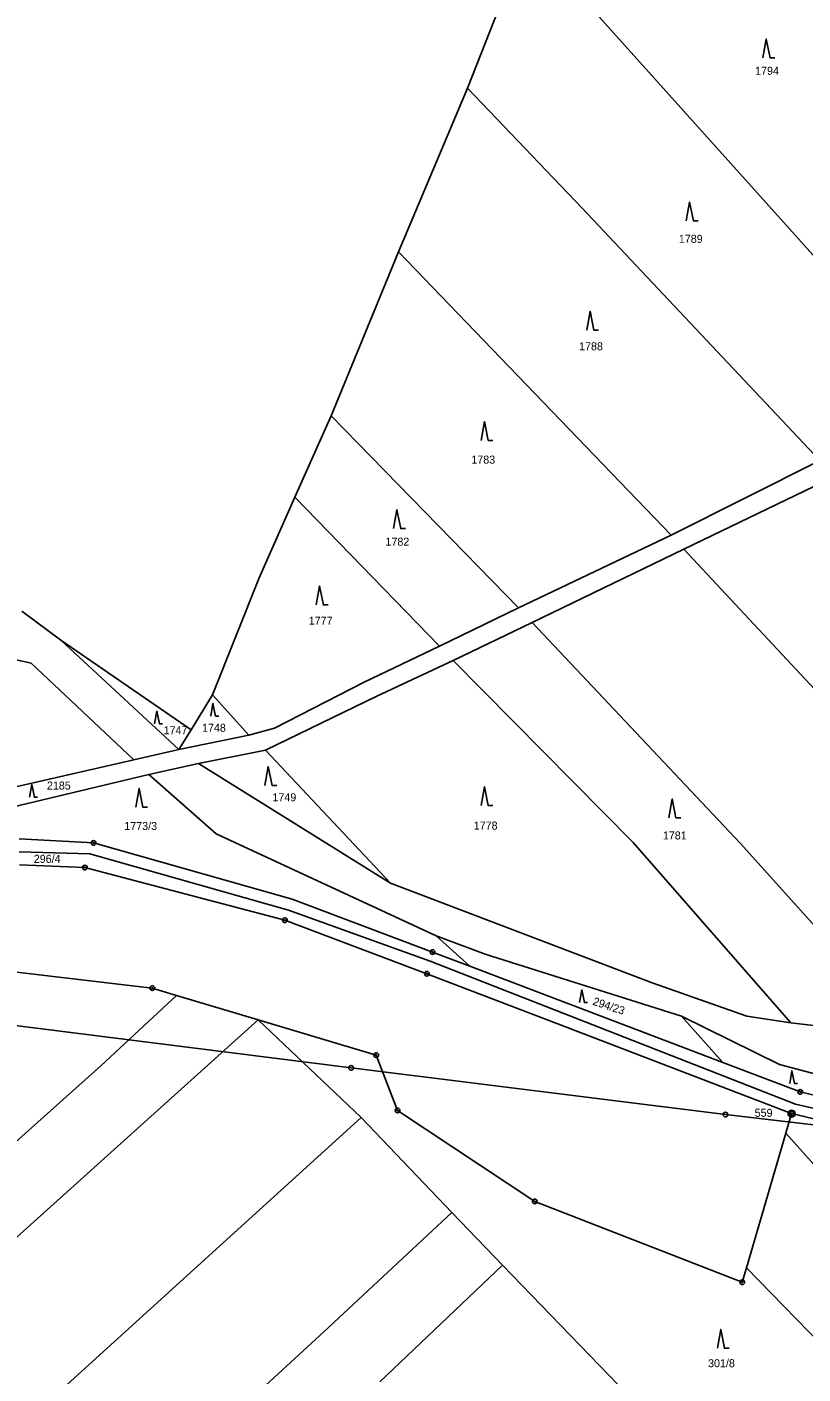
# Model space of a CAD drawing. Extents: x -762263 to -760336, y -1154405 to -1152076.
# Drawn here: x -761289.6 to -761124.8, y -1153787.3 to -1153501.2 of the extents above; entities that cross this region are included whole.
import ezdxf

# ---------------------------------------------------------------- set-up
doc = ezdxf.new("R2010")
doc.units = 0
for name, color, linetype in [('Vrstva 1', 7, 'Continuous'), ('Vrstva 10', 7, 'Continuous'), ('Vrstva 12', 7, 'Continuous'), ('Vrstva 17', 7, 'Continuous'), ('Vrstva 18', 7, 'Continuous'), ('Vrstva 24', 7, 'Continuous'), ('Vrstva 25', 7, 'Continuous'), ('Vrstva 26', 7, 'Continuous'), ('Vrstva 6', 7, 'Continuous')]:
    doc.layers.add(name, color=color, linetype=linetype)

msp = doc.modelspace()

# ---------------------------------------------------------------- linework, layer by layer
at = {"layer": 'Vrstva 1'}
for p, q in [((-761291.26, -1153673.61), (-761275.44, -1153674.5)), ((-761275.44, -1153674.5), (-761233.3, -1153686.44)), ((-761291.2, -1153679.17), (-761277.28, -1153679.74)), ((-761234.81, -1153690.92), (-761277.28, -1153679.74)), ((-761203.44, -1153697.69), (-761233.3, -1153686.44)), ((-761204.67, -1153702.27), (-761234.81, -1153690.92)), ((-761203.44, -1153697.69), (-761195.52, -1153700.7)), ((-761195.52, -1153700.7), (-761141.85, -1153721.11)), ((-761297.23, -1153701.32), (-761262.96, -1153705.34)), ((-761179.48, -1153711.94), (-761204.67, -1153702.27)), ((-761262.96, -1153705.34), (-761257.83, -1153706.88)), ((-761257.83, -1153706.88), (-761240.46, -1153712.08)), ((-761240.46, -1153712.08), (-761215.43, -1153719.57)), ((-761127.23, -1153731.99), (-761179.48, -1153711.94)), ((-761215.43, -1153719.57), (-761210.9, -1153731.31)), ((-761125.37, -1153727.38), (-761141.85, -1153721.11)), ((-761103.58, -1153732.57), (-761125.37, -1153727.38)), ((-761210.9, -1153731.31), (-761181.76, -1153750.64)), ((-761128.45, -1153736.16), (-761127.23, -1153731.99)), ((-761098.09, -1153738.93), (-761127.23, -1153731.99)), ((-761128.45, -1153736.16), (-761136.8, -1153764.7)), ((-761181.76, -1153750.64), (-761137.71, -1153767.8)), ((-761136.8, -1153764.7), (-761137.71, -1153767.8))]:
    msp.add_line(p, q, dxfattribs=at)
at = {"layer": 'Vrstva 10'}
for p, q in [((-761276.25, -1153676.81), (-761291.23, -1153676.37)), ((-761234.08, -1153688.75), (-761276.25, -1153676.81)), ((-761203.95, -1153699.6), (-761234.08, -1153688.75)), ((-761126.41, -1153729.97), (-761203.95, -1153699.6)), ((-761100.75, -1153735.85), (-761126.41, -1153729.97))]:
    msp.add_line(p, q, dxfattribs=at)
at = {"layer": 'Vrstva 12'}
for p, q in [((-761220.76, -1153722.27), (-761326.49, -1153708.93)), ((-761141.28, -1153732.19), (-761220.76, -1153722.27)), ((-761048.52, -1153743.06), (-761141.28, -1153732.19))]:
    msp.add_line(p, q, dxfattribs=at)
at = {"layer": 'Vrstva 24'}
for centre, radius in [((-761275.44, -1153674.5), 0.5), ((-761275.44, -1153674.5), 0.1), ((-761277.28, -1153679.74), 0.5), ((-761277.28, -1153679.74), 0.1), ((-761234.81, -1153690.92), 0.5), ((-761234.81, -1153690.92), 0.1), ((-761203.44, -1153697.69), 0.5), ((-761203.44, -1153697.69), 0.1), ((-761204.67, -1153702.27), 0.5), ((-761204.67, -1153702.27), 0.1), ((-761262.96, -1153705.34), 0.5), ((-761262.96, -1153705.34), 0.1), ((-761215.43, -1153719.57), 0.5), ((-761215.43, -1153719.57), 0.1), ((-761125.37, -1153727.38), 0.5), ((-761125.37, -1153727.38), 0.1), ((-761210.9, -1153731.31), 0.5), ((-761210.9, -1153731.31), 0.1), ((-761127.23, -1153731.99), 0.75), ((-761127.23, -1153731.99), 0.5), ((-761127.23, -1153731.99), 0.1), ((-761127.23, -1153731.99), 0.1), ((-761181.76, -1153750.64), 0.5), ((-761181.76, -1153750.64), 0.1), ((-761137.71, -1153767.8), 0.5), ((-761137.71, -1153767.8), 0.1)]:
    msp.add_circle(centre, radius, dxfattribs=at)
at = {"layer": 'Vrstva 25'}
for points in [[(-761133.3, -1153507.8), (-761132.6, -1153503.8), (-761131.8, -1153507.8), (-761130.8, -1153507.8)], [(-761149.58, -1153542.41), (-761148.88, -1153538.41), (-761148.08, -1153542.41), (-761147.08, -1153542.41)], [(-761170.69, -1153565.59), (-761169.99, -1153561.59), (-761169.19, -1153565.59), (-761168.19, -1153565.59)], [(-761193.13, -1153589.01), (-761192.43, -1153585.01), (-761191.63, -1153589.01), (-761190.63, -1153589.01)], [(-761211.72, -1153607.76), (-761211.02, -1153603.76), (-761210.22, -1153607.76), (-761209.22, -1153607.76)], [(-761228.15, -1153623.96), (-761227.45, -1153619.96), (-761226.65, -1153623.96), (-761225.65, -1153623.96)], [(-761262.469, -1153649.19), (-761262, -1153646.51), (-761261.464, -1153649.19), (-761260.794, -1153649.19)], [(-761250.549, -1153647.56), (-761250.08, -1153644.88), (-761249.544, -1153647.56), (-761248.874, -1153647.56)], [(-761239.04, -1153662.29), (-761238.34, -1153658.29), (-761237.54, -1153662.29), (-761236.54, -1153662.29)], [(-761289.019, -1153664.8), (-761288.55, -1153662.12), (-761288.014, -1153664.8), (-761287.344, -1153664.8)], [(-761266.47, -1153666.93), (-761265.77, -1153662.93), (-761264.97, -1153666.93), (-761263.97, -1153666.93)], [(-761193.13, -1153666.56), (-761192.43, -1153662.56), (-761191.63, -1153666.56), (-761190.63, -1153666.56)], [(-761153.27, -1153669.17), (-761152.57, -1153665.17), (-761151.77, -1153669.17), (-761150.77, -1153669.17)], [(-761172.229, -1153708.39), (-761171.76, -1153705.71), (-761171.224, -1153708.39), (-761170.554, -1153708.39)], [(-761127.609, -1153725.56), (-761127.14, -1153722.88), (-761126.604, -1153725.56), (-761125.934, -1153725.56)], [(-761142.97, -1153781.81), (-761142.27, -1153777.81), (-761141.47, -1153781.81), (-761140.47, -1153781.81)]]:
    msp.add_lwpolyline(points, dxfattribs=at)
at = {"layer": 'Vrstva 26'}
for centre in [(-761220.76, -1153722.27), (-761141.28, -1153732.19)]:
    msp.add_circle(centre, 0.5, dxfattribs=at)
at = {"layer": 'Vrstva 6'}
for p, q in [((-761196.01, -1153514.22), (-761183.36, -1153481.98)), ((-761183.36, -1153481.98), (-761106.64, -1153567.61)), ((-761210.67, -1153548.96), (-761196.01, -1153514.22)), ((-761196.01, -1153514.22), (-761171.68, -1153539.67)), ((-761171.68, -1153539.67), (-761121.21, -1153593.28)), ((-761225.01, -1153583.78), (-761210.67, -1153548.96)), ((-761152.76, -1153609.11), (-761210.67, -1153548.96)), ((-761232.73, -1153601.08), (-761225.01, -1153583.78)), ((-761225.01, -1153583.78), (-761185.2, -1153624.56)), ((-761152.76, -1153609.11), (-761121.21, -1153593.28)), ((-761150.08, -1153612.09), (-761118.57, -1153596.92)), ((-761240.3, -1153618.17), (-761232.73, -1153601.08)), ((-761232.73, -1153601.08), (-761202.01, -1153632.73)), ((-761185.2, -1153624.56), (-761152.76, -1153609.11)), ((-761182.31, -1153627.7), (-761150.08, -1153612.09)), ((-761150.08, -1153612.09), (-761049.56, -1153720.16)), ((-761250.19, -1153643.03), (-761240.3, -1153618.17)), ((-761290.69, -1153625.31), (-761282.41, -1153631.47)), ((-761202.01, -1153632.73), (-761185.2, -1153624.56)), ((-761199.1, -1153635.77), (-761182.31, -1153627.7)), ((-761182.31, -1153627.7), (-761138.14, -1153674.54)), ((-761317.63, -1153629.8), (-761288.72, -1153636.31)), ((-761257.3, -1153654.69), (-761282.41, -1153631.47)), ((-761282.41, -1153631.47), (-761254.71, -1153650.49)), ((-761218.01, -1153640.36), (-761202.01, -1153632.73)), ((-761288.72, -1153636.31), (-761266.86, -1153656.88)), ((-761215.26, -1153643.32), (-761199.1, -1153635.77)), ((-761199.1, -1153635.77), (-761160.84, -1153674.43)), ((-761237.02, -1153650.11), (-761218.01, -1153640.36)), ((-761250.19, -1153643.03), (-761254.71, -1153650.49)), ((-761250.19, -1153643.03), (-761242.44, -1153651.63)), ((-761238.94, -1153654.8), (-761215.26, -1153643.32)), ((-761254.71, -1153650.49), (-761257.3, -1153654.69)), ((-761257.3, -1153654.69), (-761242.44, -1153651.63)), ((-761242.44, -1153651.63), (-761237.02, -1153650.11)), ((-761266.86, -1153656.88), (-761257.3, -1153654.69)), ((-761253.14, -1153657.6), (-761238.94, -1153654.8)), ((-761238.94, -1153654.8), (-761212.41, -1153683.07)), ((-761326.5, -1153670.48), (-761266.86, -1153656.88)), ((-761263.67, -1153660), (-761253.14, -1153657.6)), ((-761253.14, -1153657.6), (-761212.41, -1153683.07)), ((-761324.64, -1153674.46), (-761263.67, -1153660)), ((-761263.67, -1153660), (-761249.44, -1153672.58)), ((-761249.44, -1153672.58), (-761202.67, -1153694.23)), ((-761160.84, -1153674.43), (-761127.38, -1153712.67)), ((-761138.14, -1153674.54), (-761092.02, -1153725.92)), ((-761212.41, -1153683.07), (-761156.81, -1153704.23)), ((-761202.67, -1153694.23), (-761195.52, -1153700.7)), ((-761202.67, -1153694.23), (-761192.32, -1153698.13)), ((-761192.32, -1153698.13), (-761150.6, -1153711.31)), ((-761273.91, -1153721.86), (-761257.83, -1153706.88)), ((-761156.81, -1153704.23), (-761136.75, -1153711.31)), ((-761240.46, -1153712.08), (-761310.21, -1153774.82)), ((-761218.65, -1153732.82), (-761240.46, -1153712.08)), ((-761141.85, -1153721.11), (-761150.6, -1153711.31)), ((-761150.6, -1153711.31), (-761129.76, -1153721.55)), ((-761136.75, -1153711.31), (-761127.38, -1153712.67)), ((-761127.38, -1153712.67), (-761114.6, -1153714.25)), ((-761273.91, -1153721.86), (-761338.17, -1153779.18)), ((-761129.76, -1153721.55), (-761108.04, -1153727.41)), ((-761218.65, -1153732.82), (-761311, -1153816.67)), ((-761218.65, -1153732.82), (-761199.38, -1153753)), ((-761086.16, -1153783.65), (-761128.45, -1153736.16)), ((-761199.38, -1153753), (-761226.53, -1153778.32)), ((-761199.38, -1153753), (-761188.61, -1153764.15)), ((-761214.62, -1153788.96), (-761188.61, -1153764.15)), ((-761188.61, -1153764.15), (-761161.94, -1153791.76)), ((-761136.8, -1153764.7), (-761099.25, -1153803.44)), ((-761226.53, -1153778.32), (-761310.15, -1153855))]:
    msp.add_line(p, q, dxfattribs=at)

# ---------------------------------------------------------------- texts
at = {"layer": 'Vrstva 17'}
msp.add_text('559', height=1.7, dxfattribs=at).set_placement((-761135.057, -1153732.66))
at = {"layer": 'Vrstva 18'}
for s, p in [('1794', (-761134.965, -1153511.38)), ('1789', (-761151.162, -1153547.06)), ('1788', (-761172.342, -1153569.88)), ('1783', (-761195.219, -1153593.95)), ('1782', (-761213.456, -1153611.38)), ('1777', (-761229.745, -1153628.15)), ('1747', (-761260.565, -1153651.43)), ('1748', (-761252.405, -1153650.9)), ('2185', (-761285.343, -1153663.16)), ('1749', (-761237.455, -1153665.66)), ('1773/3', (-761268.908, -1153671.75)), ('1778', (-761194.715, -1153671.66)), ('1781', (-761154.554, -1153673.77)), ('296/4', (-761288.133, -1153678.73)), ('301/8', (-761144.959, -1153785.84))]:
    msp.add_text(s, height=1.7, dxfattribs=at).set_placement(p)
msp.add_text('294/23', height=1.7, rotation=341.54014, dxfattribs=at).set_placement((-761169.583, -1153708.83))

doc.saveas('drawing.dxf')
